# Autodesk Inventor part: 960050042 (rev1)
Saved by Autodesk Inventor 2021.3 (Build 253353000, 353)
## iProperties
Created: 2023-03
Part Number: 960050042 (rev1)
Material: Generic
Description: Round Plastic Spacers WA-SPARO
Document SubType Name: Modeling
Designer: AdminForWorker
Density: 1 g/cm^3
Appearance: Default
Title: 960050042 (rev1)
Author: AdminForWorker
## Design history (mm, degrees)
feature "Composite1"
body "Srf1"
